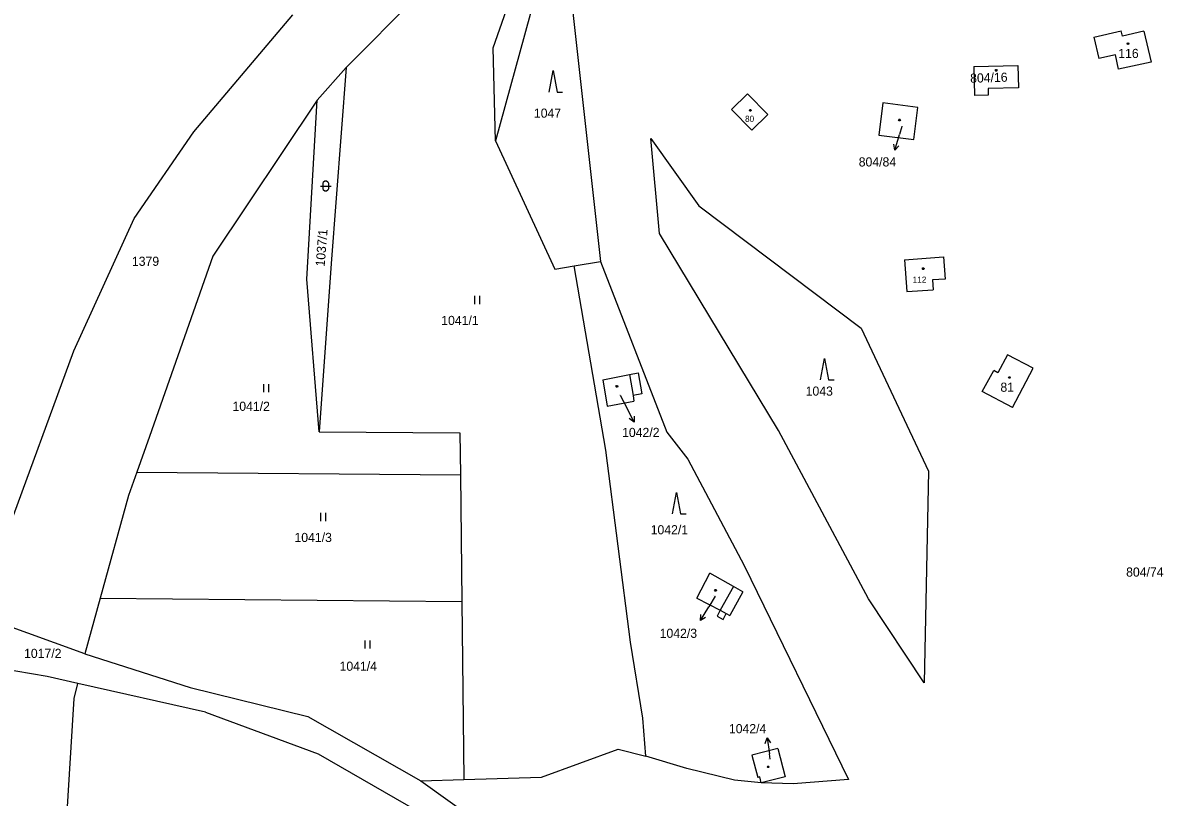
# Model space of a CAD drawing. Extents: x -845995 to -842497, y -1063614 to -1059680.
# Drawn here: x -843977.7 to -843765.8, y -1061529.9 to -1061386 of the extents above; entities that cross this region are included whole.
import ezdxf

# ---------------------------------------------------------------- set-up
doc = ezdxf.new("R2010")
doc.units = 0
for name, color, linetype in [('KN_HRANICE', 7, 'Continuous'), ('KN_KULTURY', 7, 'Continuous'), ('KN_PARCELY', 7, 'Continuous'), ('KN_SLUCKY', 7, 'Continuous'), ('KN_STAVEBNI', 7, 'Continuous')]:
    doc.layers.add(name, color=color, linetype=linetype)

# ---------------------------------------------------------------- blocks, each defined once
blk = doc.blocks.new('306')
for p, q in [((-0.5, 1.5), (-0.5, 0)), ((0.5, 0), (0.5, 1.5))]:
    blk.add_line(p, q)
blk = doc.blocks.new('308')
blk.add_lwpolyline([(-0.75, 0), (0, 4), (0.75, 0), (1.75, 0)])
blk = doc.blocks.new('316')
for points in [[(-1, 1), (0.27, 1), (1, 1)], [(-0.5, 1.5), (-0.4, 1.79), (-0.15, 1.97), (0.16, 1.97), (0.41, 1.79), (0.51, 1.5), (0.51, 0.5), (0.41, 0.21), (0.16, 0.03), (-0.15, 0.03), (-0.4, 0.21), (-0.5, 0.5), (-0.5, 1.5)]]:
    blk.add_lwpolyline(points)
blk = doc.blocks.new('10292')
blk.add_line((0, 3), (0, 0))
blk.add_lwpolyline([(-0.5, 2), (0, 3), (0.5, 2)])
blk = doc.blocks.new('402')
blk.add_lwpolyline([(0.09, 0.15), (0.18, 0), (0.09, -0.15), (-0.09, -0.15), (-0.18, 0), (-0.09, 0.15), (0.09, 0.15)])

msp = doc.modelspace()

# ---------------------------------------------------------------- linework, layer by layer
at = {"layer": 'KN_HRANICE'}
for p, q in [((-843885.63, -1061362.15), (-843917.63, -1061394.28)), ((-843877.51, -1061362.72), (-843889.86, -1061407.89)), ((-843876.82, -1061372.57), (-843870.39, -1061430.31)), ((-843890.35, -1061390.64), (-843886.98, -1061381.02)), ((-843945.96, -1061406.23), (-843927.56, -1061384.52)), ((-843778.7, -1061388.64), (-843773.62, -1061387.46)), ((-843773.38, -1061388.48), (-843773.62, -1061387.46)), ((-843769.39, -1061387.54), (-843773.38, -1061388.48)), ((-843769.39, -1061387.54), (-843768.05, -1061393.32)), ((-843778.7, -1061388.64), (-843777.77, -1061392.61)), ((-843889.86, -1061407.89), (-843890.35, -1061390.64)), ((-843801, -1061394.11), (-843792.85, -1061393.92)), ((-843792.85, -1061393.92), (-843792.73, -1061398.04)), ((-843774.7, -1061391.95), (-843777.77, -1061392.61)), ((-843774.12, -1061394.63), (-843774.7, -1061391.95)), ((-843768.05, -1061393.32), (-843774.12, -1061394.63)), ((-843917.63, -1061394.28), (-843923.01, -1061400.34)), ((-843917.63, -1061394.28), (-843920.43, -1061430.71)), ((-843801, -1061394.11), (-843800.88, -1061399.48)), ((-843792.73, -1061398.04), (-843798.36, -1061398.2)), ((-843843.05, -1061399.17), (-843846.02, -1061402.11)), ((-843839.28, -1061403.03), (-843843.05, -1061399.17)), ((-843798.33, -1061399.41), (-843800.88, -1061399.48)), ((-843798.36, -1061398.2), (-843798.33, -1061399.41)), ((-843923.01, -1061400.34), (-843942.42, -1061429.36)), ((-843924.93, -1061433.59), (-843923.01, -1061400.34)), ((-843846.02, -1061402.11), (-843842.25, -1061405.95)), ((-843817.92, -1061400.87), (-843818.66, -1061406.85)), ((-843811.38, -1061401.7), (-843817.92, -1061400.87)), ((-843812.14, -1061407.69), (-843811.38, -1061401.7)), ((-843842.25, -1061405.95), (-843839.28, -1061403.03)), ((-843957.05, -1061422.37), (-843945.96, -1061406.23)), ((-843889.86, -1061407.89), (-843878.87, -1061431.73)), ((-843859.38, -1061425.13), (-843861, -1061407.51)), ((-843861, -1061407.51), (-843852.13, -1061420.01)), ((-843818.66, -1061406.85), (-843812.14, -1061407.69)), ((-843852.13, -1061420.01), (-843821.93, -1061442.71)), ((-843968.26, -1061446.94), (-843957.05, -1061422.37)), ((-843837.3, -1061461.76), (-843859.38, -1061425.13)), ((-843942.42, -1061429.36), (-843954.19, -1061462.84)), ((-843813.86, -1061430.01), (-843806.64, -1061429.47)), ((-843806.64, -1061429.47), (-843806.33, -1061433.59)), ((-843920.43, -1061430.71), (-843922.68, -1061461.95)), ((-843878.87, -1061431.73), (-843875.25, -1061431.15)), ((-843875.25, -1061431.15), (-843870.39, -1061430.31)), ((-843869.38, -1061465.39), (-843875.25, -1061431.15)), ((-843870.39, -1061430.31), (-843858.02, -1061462.05)), ((-843813.86, -1061430.01), (-843813.48, -1061435.92)), ((-843922.68, -1061461.95), (-843924.93, -1061433.59)), ((-843806.33, -1061433.59), (-843808.67, -1061433.76)), ((-843808.67, -1061433.76), (-843808.54, -1061435.61)), ((-843813.48, -1061435.92), (-843808.54, -1061435.61)), ((-843821.93, -1061442.71), (-843809.45, -1061469.26)), ((-843980.83, -1061481.23), (-843968.26, -1061446.94)), ((-843794.77, -1061447.65), (-843796.56, -1061450.99)), ((-843789.99, -1061450.16), (-843794.77, -1061447.65)), ((-843864.96, -1061451.3), (-843863.38, -1061451.03)), ((-843863.38, -1061451.03), (-843862.68, -1061454.92)), ((-843799.45, -1061454.51), (-843797.31, -1061450.58)), ((-843796.56, -1061450.99), (-843797.31, -1061450.58)), ((-843793.84, -1061457.48), (-843789.99, -1061450.16)), ((-843869.96, -1061452.32), (-843864.96, -1061451.3)), ((-843869.96, -1061452.32), (-843869.16, -1061457.2)), ((-843862.68, -1061454.92), (-843864.28, -1061455.21)), ((-843864.28, -1061455.21), (-843864.18, -1061456.29)), ((-843793.84, -1061457.48), (-843799.45, -1061454.51)), ((-843869.16, -1061457.2), (-843864.18, -1061456.29)), ((-843954.19, -1061462.84), (-843956.53, -1061469.46)), ((-843922.68, -1061461.95), (-843896.5, -1061462.18)), ((-843896.5, -1061462.18), (-843896.4, -1061469.99)), ((-843858.02, -1061462.05), (-843854.15, -1061467.05)), ((-843820.56, -1061493), (-843837.3, -1061461.76)), ((-843864.77, -1061501.08), (-843869.38, -1061465.39)), ((-843854.15, -1061467.05), (-843843.68, -1061486.84)), ((-843956.53, -1061469.46), (-843958.07, -1061473.83)), ((-843956.53, -1061469.46), (-843896.4, -1061469.99)), ((-843896.4, -1061469.99), (-843896.13, -1061493.5)), ((-843809.45, -1061469.26), (-843810.2, -1061508.62)), ((-843958.07, -1061473.83), (-843963.35, -1061492.91)), ((-843843.68, -1061486.84), (-843824.29, -1061526.58)), ((-843852.46, -1061492.86), (-843850.07, -1061488.22)), ((-843845.66, -1061490.69), (-843850.07, -1061488.22)), ((-843843.9, -1061491.68), (-843845.66, -1061490.69)), ((-843963.35, -1061492.91), (-843966.19, -1061503.2)), ((-843963.35, -1061492.91), (-843896.13, -1061493.5)), ((-843896.13, -1061493.5), (-843895.75, -1061526.56)), ((-843852.46, -1061492.86), (-843848.11, -1061495.14)), ((-843843.9, -1061491.68), (-843846.35, -1061496.07)), ((-843810.2, -1061508.62), (-843820.56, -1061493)), ((-843848.11, -1061495.14), (-843848.69, -1061496.25)), ((-843966.19, -1061503.2), (-843982.66, -1061497.25)), ((-843848.69, -1061496.25), (-843847.59, -1061496.83)), ((-843847.59, -1061496.83), (-843847.01, -1061495.72)), ((-843847.01, -1061495.72), (-843846.35, -1061496.07)), ((-843862.53, -1061515.15), (-843864.77, -1061501.08)), ((-843966.19, -1061503.2), (-843946.63, -1061509.49)), ((-843973.2, -1061507.42), (-843982, -1061505.94)), ((-843967.5, -1061508.71), (-843973.2, -1061507.42)), ((-843968.17, -1061511.54), (-843967.5, -1061508.71)), ((-843943.75, -1061514.08), (-843967.5, -1061508.71)), ((-843946.63, -1061509.49), (-843924.78, -1061514.87)), ((-843970.29, -1061545.7), (-843968.17, -1061511.54)), ((-843943.75, -1061514.08), (-843922.86, -1061521.79)), ((-843924.78, -1061514.87), (-843903.73, -1061526.81)), ((-843861.92, -1061522.26), (-843862.53, -1061515.15)), ((-843881.36, -1061526.12), (-843867.08, -1061520.93)), ((-843867.08, -1061520.93), (-843861.92, -1061522.26)), ((-843837.41, -1061520.83), (-843842.24, -1061522.05)), ((-843837.41, -1061520.83), (-843836.05, -1061526.07)), ((-843922.86, -1061521.79), (-843904.45, -1061532.36)), ((-843854.35, -1061524.5), (-843861.92, -1061522.26)), ((-843842.24, -1061522.05), (-843841.16, -1061526.18)), ((-843845.47, -1061526.72), (-843854.35, -1061524.5)), ((-843903.73, -1061526.81), (-843895.75, -1061526.56)), ((-843903.73, -1061526.81), (-843864.94, -1061554.51)), ((-843895.75, -1061526.56), (-843881.36, -1061526.12)), ((-843840.51, -1061527.19), (-843845.47, -1061526.72)), ((-843840.76, -1061526.09), (-843841.16, -1061526.18)), ((-843840.51, -1061527.19), (-843840.76, -1061526.09)), ((-843836.05, -1061526.07), (-843840.51, -1061527.19)), ((-843834.58, -1061527.35), (-843840.51, -1061527.19)), ((-843824.29, -1061526.58), (-843834.58, -1061527.35))]:
    msp.add_line(p, q, dxfattribs=at)
at = {"layer": 'KN_PARCELY'}
for p, q in [((-843814.36, -1061405.27), (-843814.81, -1061406.76)), ((-843866.69, -1061455.18), (-843865.5, -1061457.51)), ((-843849.05, -1061492.49), (-843850.26, -1061494.49)), ((-843838.84, -1061522.81), (-843838.98, -1061521.8))]:
    msp.add_line(p, q, dxfattribs=at)
at = {"layer": 'KN_SLUCKY'}
for p, q in [((-843864.96, -1061451.3), (-843864.28, -1061455.21)), ((-843845.66, -1061490.69), (-843848.11, -1061495.14)), ((-843848.11, -1061495.14), (-843847.01, -1061495.72))]:
    msp.add_line(p, q, dxfattribs=at)
at = {"layer": 'KN_STAVEBNI'}
for p, q in [((-843778.7, -1061388.64), (-843773.62, -1061387.46)), ((-843773.38, -1061388.48), (-843773.62, -1061387.46)), ((-843769.39, -1061387.54), (-843773.38, -1061388.48)), ((-843769.39, -1061387.54), (-843768.05, -1061393.32)), ((-843778.7, -1061388.64), (-843777.77, -1061392.61)), ((-843801, -1061394.11), (-843792.85, -1061393.92)), ((-843792.85, -1061393.92), (-843792.73, -1061398.04)), ((-843774.7, -1061391.95), (-843777.77, -1061392.61)), ((-843774.12, -1061394.63), (-843774.7, -1061391.95)), ((-843768.05, -1061393.32), (-843774.12, -1061394.63)), ((-843801, -1061394.11), (-843800.88, -1061399.48)), ((-843792.73, -1061398.04), (-843798.36, -1061398.2)), ((-843843.05, -1061399.17), (-843846.02, -1061402.11)), ((-843839.28, -1061403.03), (-843843.05, -1061399.17)), ((-843798.33, -1061399.41), (-843800.88, -1061399.48)), ((-843798.36, -1061398.2), (-843798.33, -1061399.41)), ((-843846.02, -1061402.11), (-843842.25, -1061405.95)), ((-843817.92, -1061400.87), (-843818.66, -1061406.85)), ((-843811.38, -1061401.7), (-843817.92, -1061400.87)), ((-843812.14, -1061407.69), (-843811.38, -1061401.7)), ((-843842.25, -1061405.95), (-843839.28, -1061403.03)), ((-843818.66, -1061406.85), (-843812.14, -1061407.69)), ((-843813.86, -1061430.01), (-843806.64, -1061429.47)), ((-843806.64, -1061429.47), (-843806.33, -1061433.59)), ((-843813.86, -1061430.01), (-843813.48, -1061435.92)), ((-843806.33, -1061433.59), (-843808.67, -1061433.76)), ((-843808.67, -1061433.76), (-843808.54, -1061435.61)), ((-843813.48, -1061435.92), (-843808.54, -1061435.61)), ((-843794.77, -1061447.65), (-843796.56, -1061450.99)), ((-843789.99, -1061450.16), (-843794.77, -1061447.65)), ((-843799.45, -1061454.51), (-843797.31, -1061450.58)), ((-843796.56, -1061450.99), (-843797.31, -1061450.58)), ((-843793.84, -1061457.48), (-843789.99, -1061450.16)), ((-843869.96, -1061452.32), (-843864.96, -1061451.3)), ((-843869.96, -1061452.32), (-843869.16, -1061457.2)), ((-843864.96, -1061451.3), (-843864.28, -1061455.21)), ((-843864.28, -1061455.21), (-843864.18, -1061456.29)), ((-843793.84, -1061457.48), (-843799.45, -1061454.51)), ((-843869.16, -1061457.2), (-843864.18, -1061456.29)), ((-843852.46, -1061492.86), (-843850.07, -1061488.22)), ((-843845.66, -1061490.69), (-843850.07, -1061488.22)), ((-843845.66, -1061490.69), (-843848.11, -1061495.14)), ((-843852.46, -1061492.86), (-843848.11, -1061495.14)), ((-843837.41, -1061520.83), (-843842.24, -1061522.05)), ((-843837.41, -1061520.83), (-843836.05, -1061526.07)), ((-843842.24, -1061522.05), (-843841.16, -1061526.18)), ((-843840.76, -1061526.09), (-843841.16, -1061526.18)), ((-843840.51, -1061527.19), (-843840.76, -1061526.09)), ((-843836.05, -1061526.07), (-843840.51, -1061527.19))]:
    msp.add_line(p, q, dxfattribs=at)

# ---------------------------------------------------------------- block references
at = {"layer": 'KN_KULTURY'}
for name, p in [('402', (-843772.35, -1061389.84)), ('308', (-843879.17, -1061398.87)), ('402', (-843796.85, -1061394.84)), ('402', (-843842.53, -1061402.26)), ('402', (-843814.81, -1061404.02)), ('316', (-843921.43, -1061417.31)), ('402', (-843810.39, -1061431.68)), ('306', (-843893.31, -1061438.23)), ('308', (-843828.73, -1061452.33)), ('306', (-843932.52, -1061454.62)), ('402', (-843794.38, -1061451.88)), ('402', (-843867.33, -1061453.53)), ('308', (-843856.23, -1061477.22)), ('306', (-843921.89, -1061478.55)), ('402', (-843848.98, -1061491.41)), ('306', (-843913.69, -1061502.25)), ('402', (-843839.22, -1061524.22))]:
    msp.add_blockref(name, p, dxfattribs=at)
at = {"layer": 'KN_PARCELY'}
for p, rotation in [((-843814.81, -1061406.76), 163.063788), ((-843865.5, -1061457.51), -152.99034900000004), ((-843850.26, -1061494.49), 148.854435), ((-843838.98, -1061521.8), 8.136001)]:
    msp.add_blockref('10292', p, dxfattribs=dict(at, rotation=rotation))

# ---------------------------------------------------------------- texts
for s, height, p in [('116', 1.7, (-843774.16, -1061392.53)), ('1047', 1.7, (-843882.75, -1061403.62)), ('80', 1.14, (-843843.51, -1061404.39)), ('804/84', 0.1, (-843814.65, -1061405.27)), ('804/84', 1.7, (-843822.39, -1061412.68)), ('1379', 1.7, (-843957.45, -1061431.14)), ('112', 1.14, (-843812.37, -1061434.28)), ('1041/1', 1.7, (-843899.97, -1061442.13)), ('81', 1.7, (-843796.06, -1061454.54)), ('1042/2', 0.1, (-843866.99, -1061455.18)), ('1043', 1.7, (-843832.25, -1061455.26)), ('1041/2', 1.7, (-843938.76, -1061458.08)), ('1042/2', 1.7, (-843866.36, -1061462.94)), ('1041/3', 1.7, (-843927.24, -1061482.45)), ('1042/1', 1.7, (-843861.05, -1061481.02)), ('804/74', 1.7, (-843772.7, -1061488.88)), ('1042/3', 0.1, (-843849.35, -1061492.49)), ('1042/3', 1.7, (-843859.38, -1061500.25)), ('1017/2', 1.7, (-843977.49, -1061503.99)), ('1041/4', 1.7, (-843918.86, -1061506.37)), ('1042/4', 1.7, (-843846.51, -1061517.97)), ('1042/4', 0.1, (-843839.14, -1061522.81))]:
    msp.add_text(s, height=height, dxfattribs=at).set_placement(p)
for s, rotation, p in [('804/16', 1.776, (-843801.66, -1061397.14)), ('1037/1', 85.428, (-843921.64, -1061431.32))]:
    msp.add_text(s, height=1.7, rotation=rotation, dxfattribs=at).set_placement(p)

doc.saveas('drawing.dxf')
